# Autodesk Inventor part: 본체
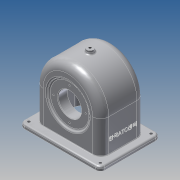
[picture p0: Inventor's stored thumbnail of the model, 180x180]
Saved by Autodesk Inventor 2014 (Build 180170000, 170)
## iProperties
Created: 2016-01
Part Number: 본체
Material: Aluminum 6061
Document SubType Name: Modeling
Designer: user
Density: 2.71 g/cm^3
Appearance: Aluminum - Flat
Mass: 849.26 g
Surface Area: 1020.34 cm^2
Volume: 313.38 cm^3
Author: user
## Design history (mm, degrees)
sketch "Sketch1"
  geometry: L1 (-57, 0)-(57, 0); L2 (57, 0)-(57, -57); L3 (57, -57)-(-57, -57); L4 (-57, -57)-(-57, 0); A1 r 57 centre (0, 0) between (57, 0) and (-57, 0); 2 further points
  constraints: 8 end point, 2 coincident, 2 point on circle, 1 centre point, 1 midpoint
  dimensions: "d1" = 114 distance of L1.start L1.end; "d3" = 57 distance of L1.end L2.end
extrude "Extrusion1" new body sketch "Sketch1" stored distance "d4" = 77; taper "d5" = 0 deg
workplane "Work Plane1"
sketch "Sketch3"
  geometry: L1 (-70, -52)-(70, -52); L2 (70, -52)-(70, 52); L3 (70, 52)-(-70, 52); L4 (-70, 52)-(-70, -52); 3 further points
  constraints: 8 end point, 2 midpoint, 1 horizontal alignment, 1 vertical alignment
  dimensions: "d10" = 140 distance of L2.end L3.end; "d11" = 104 distance of L3.end L1.start
extrude "Extrusion2" join sketch "Sketch3" distance "d12" = 7; taper "d13" = 0 deg
sketch "Sketch4"
  geometry: L1 (70, 64)-(-70, 64) reference; C1 r 35.256 at (0, 4)
  constraints: 1 centre point
  dimensions: "d113" = 60 distance from line of L1 C1.centre
extrude "Extrusion3" join sketch "Sketch4" distance "d14" = 10; taper "d15" = 0 deg
sketch "Sketch5"
  geometry: L1 (57, 0)-(57, -57) reference; L2 (-57, -57)-(-57, 0) reference; L3 (70, -64)-(-70, -64) reference; L4 (-51, -64)-(-51, 0); L5 (51, 0)-(51, -64); L6 (-51, -64)-(51, -64); A1 r 57 centre (0, 0) between (57, 0) and (-57, 0) reference; A2 r 51 centre (0, 0) between (51, 0) and (-51, 0); 1 further point
  constraints: 6 end point, 2 point on circle, 2 point on line, 1 centre point
  dimensions: "d16" = 6 radial gap between concentric circles of A1 A2
extrude "Extrusion4" cut sketch "Sketch5" stored distance "d17" = 67; taper "d18" = 0 deg
sketch "Sketch6"
  geometry: L1 (-38.5, 0)-(-38.5, -57) reference; L2 (-33.5, 35.747)-(-19.5, 24); L3 (-19.5, 24)-(-19.5, -4); L4 (-33.5, 35.747)-(-33.5, -4); L5 (-38.5, 57)-(-38.5, 0) reference; L6 (-38.5, -4)-(44.143, -4); L7 (33.5, -64)-(-33.5, -64) reference; 1 further point
  constraints: 8 end point, 3 point on line
  dimensions: "d20" = 50 deg angle of L3 L2; "d27" = 5 distance between parallel lines of L5 L4; "d28" = 19 distance between parallel lines of L5 L3; "d114" = 60 distance between parallel lines of L7 L6; "d115" = 56 diameter of L2.end L6
revolve "Revolution1" sketch "Sketch6" stored, may be unused: angle "d29" = 90 deg
fillet "Fillet1" dims "d39" = 9
sketch "Sketch7"
  geometry: L1 (-33.5, 35.747)-(-19.5, 24) reference; L2 (-35.5, 30.899)-(-38.5, 33.416); L3 (-35.5, -4)-(-35.5, 30.899); L4 (-38.5, -4)-(0, -4); L5 (24.5, -64)-(-24.5, -64) reference; L6 (-38.5, 33.416)-(-38.5, -4); 2 further points
  constraints: 8 end point, 1 point on line
  dimensions: "d125" = 60 distance between parallel lines of L5 L4; "d126" = 5 distance between parallel lines of L1 L2; "d127" = 3 distance between parallel lines of L3 L6
revolve "Revolution2" sketch "Sketch7" stored, may be unused: angle "d52" = 90 deg
workplane "Work Plane3"
  workplane "Work Plane2"
sketch "Sketch8"
  geometry: C1 r 6 at (0, 0); 1 further point
  constraints: 1 centre point, 1 coincident
extrude "Extrusion5" join sketch "Sketch8" stored distance "d55" = 67; taper "d56" = 0 deg
fillet "Fillet2" dims "d57" = 3
fillet "Fillet4" dims "d59" = 3
sketch "Sketch9"
  geometry: L1 (-62, 44)-(62, 44); L2 (62, 44)-(62, -44); L3 (62, -44)-(-62, -44); L4 (-62, -44)-(-62, 44); 7 further points
  constraints: 8 end point, 4 coincident, 2 midpoint, 1 horizontal alignment, 1 vertical alignment
  dimensions: "d60" = 88 distance of L3.end L1.start; "d61" = 124 distance of L1.start L1.end
hole "Hole3" sketch "Sketch9" at (-62, -44), (62, -44), (62, 44), (-62, 44) diameter "d62" = 5; stored, may be unused: countersink angle "d66" = 90 deg, drill point angle "d68" = 0 deg; dims "d63" = 6, "d64" = 4, "d65" = 2, "d67" = 16
fillet "Fillet5" dims "d69" = 8
hole "Hole6" diameter "d96" = 4.459; stored, may be unused: countersink angle "d100" = 90 deg, drill point angle "d102" = 0 deg; dims "d97" = 13, "d98" = 4, "d99" = 2, "d101" = 13, "d103" = 10, "d104" = 10
workplane "Work Plane4"
sketch "Sketch12"
  geometry: L1 (-44, -64)-(44, -64) reference; L2 (-38.5, -57)-(-38.5, 0) reference; 4 further points
  constraints: 1 coincident, 1 other
  dimensions: "d106" = 30 distance from line of L1 point (0, -34); "d107" = 38.5 distance from line of L2 point (0, -34)
emboss "Emboss1" sketch "Sketch12" dims "d108" = 0.5, "d109" = 0
fillet "Fillet7" dims "d110" = 14
fillet "Fillet8" dims "d111" = 1
hole "Hole7" diameter "d118" = 40; stored, may be unused: countersink angle "d122" = 90 deg, drill point angle "d124" = 0 deg; dims "d116" = 10, "d117" = 10, "d119" = 12, "d120" = 4, "d121" = 2, "d123" = 15
hole "Hole8" diameter "d130" = 40; stored, may be unused: countersink angle "d134" = 90 deg, drill point angle "d136" = 0 deg; dims "d128" = 10, "d129" = 10, "d131" = 12, "d132" = 4, "d133" = 2, "d135" = 16
fillet "Fillet9" dims "d137" = 3
chamfer "Chamfer2" distance "d138" = 1; stored, may be unused: second distance "d139" = 2, angle "d140" = 45 deg
fillet "Fillet10" dims "d141" = 3
sketch "Sketch13"
  geometry: C1 r 21 at (0, 0) reference; 3 further points
  constraints: 1 coincident, 1 vertical alignment, 2 other
hole "Hole9" sketch "Sketch13" at (0, 28) diameter "d142" = 2.459; stored, may be unused: countersink angle "d146" = 90 deg, drill point angle "d148" = 120 deg; dims "d143" = 7, "d144" = 4, "d145" = 2, "d147" = 9
pattern_circular "Circular Pattern3" dims angle "d150" = 360 deg
sketch "Sketch14" dims "d152" = 48
  geometry: C1 r 21 at (0, 0) reference; 3 further points
  constraints: 1 coincident, 1 vertical alignment, 2 other
hole "Hole10" sketch "Sketch14" at (0, 24) diameter "d153" = 2.459; stored, may be unused: countersink angle "d157" = 90 deg, drill point angle "d159" = 120 deg; dims "d154" = 6, "d155" = 4, "d156" = 2, "d158" = 8
pattern_circular "Circular Pattern4" dims angle "d161" = 360 deg
body "Solid1"
other parameters: "d6" = -64, "d53" = -64, "d54" = 127, "d105" = 123.75
